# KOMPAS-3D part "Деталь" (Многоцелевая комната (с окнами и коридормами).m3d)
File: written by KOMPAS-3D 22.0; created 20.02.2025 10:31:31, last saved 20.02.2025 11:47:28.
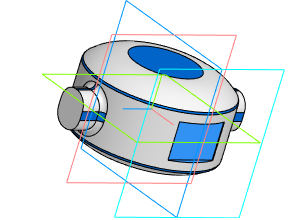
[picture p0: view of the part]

Document properties: Автор: Пользователь Windows; Полное имя файла: C:\Users\Student\Documents\Картошечка\База Сабнатика\Многоцелевая комната\Многоцелевая комната (с окнами и коридормами).m3d

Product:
- Part/product: Деталь
    Масса: 0.430417

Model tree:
1. Эскиз:3
2. Элемент вращения:1
     Угол 1 = 360
3. Скругление:1  (with: Элемент вращения:1)
     Радиус = 1
4. Смещенная плоскость:1
     Расстояние = 25
5. Эскиз:4
6. Элемент выдавливания:1
     Расстояние 2 = 2
7. Зеркальный массив:1
8. Экземпляр ( 1 )
9. Экземпляр ( 2 )  (with: Элемент выдавливания:1)
10. Эскиз:5
11. Элемент выдавливания:2
     Расстояние 1 = 65
12. Скругление:2  (with: Элемент выдавливания:2)
     Радиус = 2
13. Скругление:3  (with: Элемент выдавливания:2)
     Радиус = 2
